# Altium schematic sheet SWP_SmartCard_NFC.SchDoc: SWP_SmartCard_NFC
size A3; DocumentNumber: MB1144; Revision: C-02; SheetNumber: 8; SheetTotal: 25; Project: STM32L476G-EVAL
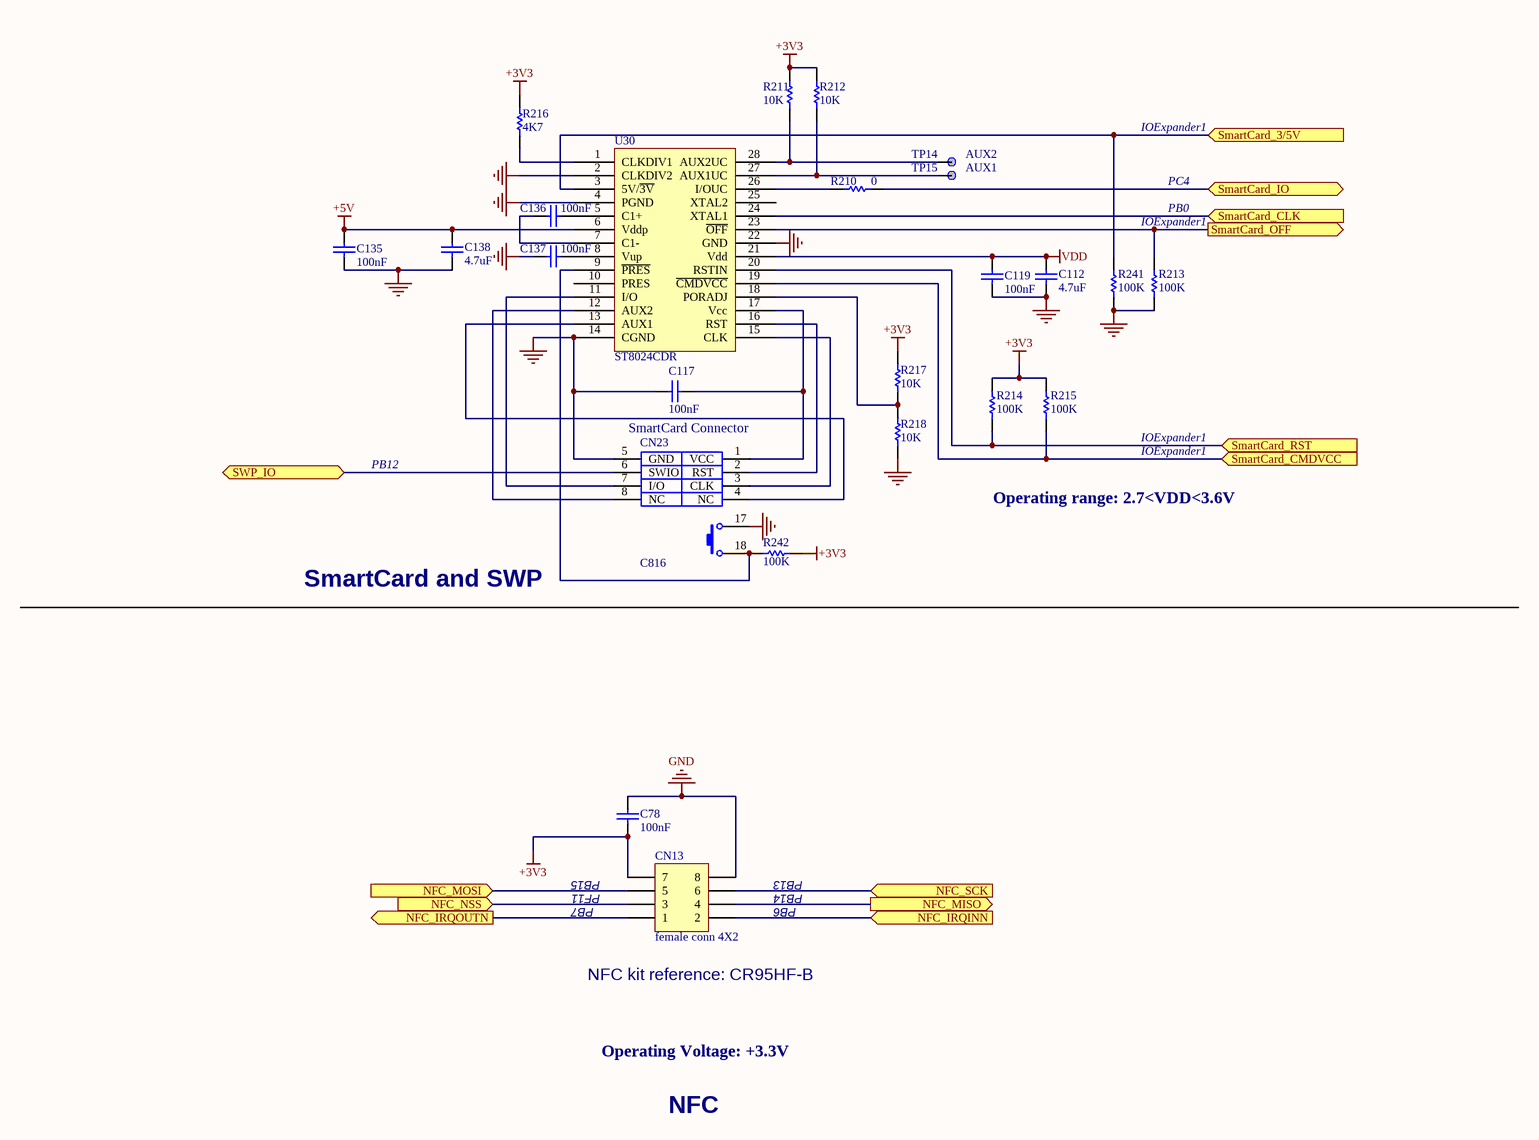
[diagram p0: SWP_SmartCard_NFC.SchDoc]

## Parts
C78  100nF  [0402C]
C112  4.7uF  [0603C]
C117  100nF  [0402C]
C119  100nF  [0402C]
C135  100nF  [0402C]
C136  100nF  [0402C]
C137  100nF  [0402C]
C138  4.7uF  [0603C]
CN13  female conn 4X2  [HDR_2X4_2R54_N]
CN23  C816  [sam_c816]
R210  0  [0603R]
R211  10K  [0402R]
R212  10K  [0402R]
R213  100K  [0402R]
R214  100K  [0402R]
R215  100K  [0402R]
R216  4K7  [0402R]
R217  10K  [0402R]
R218  10K  [0402R]
R241  100K  [0402R]
R242  100K  [0402R]
TP14  TP Name: AUX2  [TP]  (hidden comment: [N/A])
TP15  TP Name: AUX1  [TP]  (hidden comment: [N/A])
U30  ST8024CDR  [SOIC28W_1R27_17R9X10R325]

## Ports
NFC_IRQINN (in), NFC_IRQOUTN (out), NFC_MISO (out), NFC_MOSI (in), NFC_NSS (in), NFC_SCK (in), SmartCard_3/5V (in), SmartCard_CLK (in), SmartCard_CMDVCC (in), SmartCard_IO (bidir), SmartCard_OFF (out), SmartCard_RST (in), SWP_IO (bidir)

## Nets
+3V3: C78.2 CN13.7 R211.1 R212.1 R214.1 R215.1 R216.1 R217.1 R242.1
+5V: C135.1 C138.1 U30.6(Vddp)
GND: C78.1 C112.2 C117.1 C119.2 C135.2 C137.2 C138.2 CN13.8 CN23.5(GND) CN23.17 R213.2 R218.2 R241.2 U30.2(CLKDIV2) U30.4(PGND) U30.14(CGND) U30.22(GND)
VDD: C112.1 C119.1 U30.21(Vdd)
NFC_IRQINN: CN13.2 ; port NFC_IRQINN
NFC_IRQOUTN: CN13.1 ; port NFC_IRQOUTN
NFC_MISO: CN13.4 ; port NFC_MISO
NFC_MOSI: CN13.5 ; port NFC_MOSI
NFC_NSS: CN13.3 ; port NFC_NSS
NFC_SCK: CN13.6 ; port NFC_SCK
SmartCard_3/5V: R241.1 U30.3(5V/~{3V}) ; port SmartCard_3/5V
SmartCard_CLK: U30.24(XTAL1) ; port SmartCard_CLK
SmartCard_CMDVCC: R215.2 U30.19(~{CMDVCC}) ; port SmartCard_CMDVCC
SmartCard_IO: R210.2 ; port SmartCard_IO
SmartCard_OFF: R213.1 U30.23(~{OFF}) ; port SmartCard_OFF
SmartCard_RST: R214.2 U30.20(RSTIN) ; port SmartCard_RST
SWP_IO: CN23.6(SWIO) ; port SWP_IO
NetC117_2: C117.2 CN23.1(VCC) U30.17(Vcc)
NetC136_1: C136.1 U30.7(C1-)
NetC136_2: C136.2 U30.5(C1+)
NetC137_1: C137.1 U30.8(Vup)
NetCN23_2: CN23.2(RST) U30.16(RST)
NetCN23_3: CN23.3(CLK) U30.15(CLK)
NetCN23_4: CN23.4(NC) U30.13(AUX1)
NetCN23_7: CN23.7(I/O) U30.11(I/O)
NetCN23_8: CN23.8(NC) U30.12(AUX2)
NetCN23_18: CN23.18 R242.2 U30.9(~{PRES})
NetR210_1: R210.1 U30.26(I/OUC)
NetR211_2: R211.2 TP14.1 U30.28(AUX2UC)
NetR212_2: R212.2 TP15.1 U30.27(AUX1UC)
NetR216_2: R216.2 U30.1(CLKDIV1)
NetR217_2: R217.2 R218.1 U30.18(PORADJ)

Not connected (* = marked no-connect by the designer): U30 10(PRES) 25(XTAL2)

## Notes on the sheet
- IOExpander1
- PC4
- PB0
- (near CN23) SmartCard Connector
- PB12
- Operating range: 2.7<VDD<3.6V
- SmartCard and SWP
- PB7
- PB15
- PF11
- PB6
- PB14
- PB13
- (near CN13) NFC kit reference: CR95HF-B
- Operating Voltage: +3.3V
- NFC

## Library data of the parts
C78 = CAP: Capacitor; Value: 100pF; Ordered by: Subcon; ECCN_US/EU: NA
C112 C138 = Cap: Capacitor; Value: 10nF; Ordered by: Subcon; ECCN_US/EU: NA
C117 C119 C135-C137 = CAP: Capacitor; Ordered by: Subcon; ECCN_US/EU: NA
CN13 = female conn 4X2: female conn 4X2 4-Pin, Dual row; Ordered by: Subcon; ECCN_US/EU: NA; Comments: NFC connector
CN23 = Smart_card_CN: Ordered by: Subcon; Comments: Smartcard "GSM file and SWP" conenctor; ECCN_US/EU: NA; Assembly: with ST smartcard 8000080
R210-R218 R241 R242 = Res1: Resistor; Value: 1K; Ordered by: Subcon; ECCN_US/EU: NA
TP14 TP15 = TP: Ordered by: Subcon; Fitted or not fitted: NO; ECCN_US/EU: NA; Fitted: NO
U30 = ST8024CTR: Ordered by: ST; ECCN_US/EU: EAR99/NEC; Ref St: 9177802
